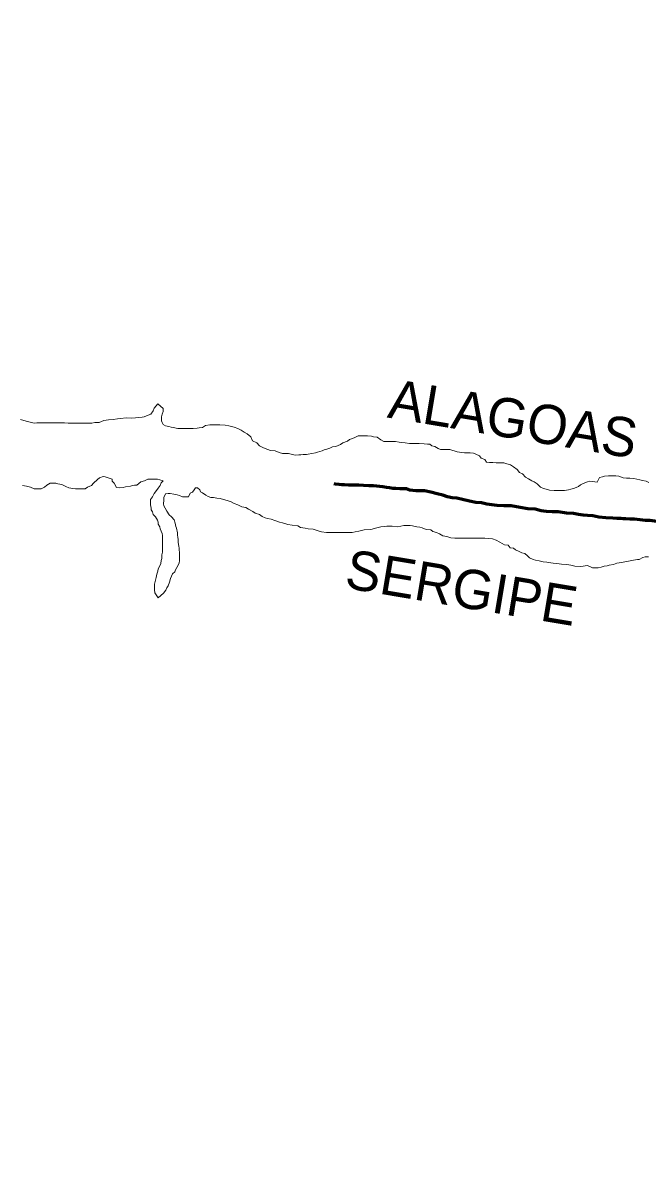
# Model space of a CAD drawing. Extents: x -1643653 to 4543381, y 1624270 to 13878484.
# Drawn here: x 657461 to 663836, y 8915829 to 8927410 of the extents above; entities that cross this region are included whole.
import ezdxf
from ezdxf.enums import TextEntityAlignment as Align

# ---------------------------------------------------------------- set-up
doc = ezdxf.new("R2010")
doc.units = 0
doc.header["$LTSCALE"] = 200
doc.linetypes.add('LONG_DASH_SHORT_DASH', pattern=[9.9, 6, -1.2, 1.5, -1.2])
for name, color, linetype, lineweight in [('23', 7, 'Continuous', 13), ('25', 7, 'Continuous', 13), ('60', 7, 'Continuous', 13), ('7', 7, 'LONG_DASH_SHORT_DASH', 60)]:
    doc.layers.add(name, color=color, linetype=linetype, lineweight=lineweight)
doc.layers.add('42', color=7, linetype='Continuous')

msp = doc.modelspace()

# ---------------------------------------------------------------- linework, layer by layer
at = {"layer": '23'}
for points in [[(660111.1, 8923015.3), (660078.7, 8923025.6), (660038.8, 8923043.3), (659988.8, 8923048.7), (659963.8, 8923056.4), (659919, 8923074.2), (659876.6, 8923094.5), (659849.3, 8923124.7), (659807, 8923147.5), (659789.7, 8923185.2), (659752.5, 8923218), (659720.1, 8923235.7), (659690.2, 8923256), (659655.3, 8923271.2), (659617.9, 8923284), (659565.5, 8923299.3), (659528.1, 8923307.1), (659473.1, 8923310), (659425.5, 8923310.3), (659370.5, 8923308.1), (659327.9, 8923300.9), (659295.3, 8923283.6), (659262.7, 8923278.8), (659240.2, 8923273.9), (659200.1, 8923271.7), (659177.6, 8923271.9), (659142.6, 8923272.1), (659120.1, 8923272.2), (659075.1, 8923272.5), (659045.1, 8923272.7), (658997.6, 8923280.6), (658975.1, 8923285.7), (658952.7, 8923290.9), (658917.7, 8923298.6), (658895.3, 8923311.3), (658883, 8923331.4), (658878.1, 8923351.4), (658878.2, 8923371.5), (658878.4, 8923391.5), (658886.1, 8923419), (658893.8, 8923444), (658894.1, 8923476.5), (658839.4, 8923524.4), (658801.5, 8923479.6), (658791.3, 8923452.2), (658768.6, 8923417.3), (658741, 8923407.4), (658700.8, 8923390.2), (658680.8, 8923387.8), (658645.7, 8923383), (658610.7, 8923380.8), (658568.2, 8923378.5), (658518.2, 8923378.9), (658460.6, 8923374.2), (658428, 8923369.5), (658383, 8923364.7), (658337.9, 8923360), (658290.3, 8923352.8), (658242.7, 8923333.1), (658197.7, 8923333.4), (658167.6, 8923326.1), (658110.1, 8923326.5), (658082.6, 8923326.7), (658027.5, 8923327), (657992.5, 8923327.3), (657945, 8923327.6), (657925, 8923327.7), (657887.5, 8923328), (657862.5, 8923328.1), (657805, 8923328.5), (657732.4, 8923329), (657664.9, 8923329.4), (657624.9, 8923329.7), (657604.9, 8923329.8), (657577.3, 8923327.5), (657495, 8923348.1), (657437.6, 8923363.5)], [(660111.1, 8923015.3), (660078.7, 8923025.6), (660038.8, 8923043.3), (659988.8, 8923048.7), (659963.8, 8923056.4), (659919, 8923074.2), (659876.6, 8923094.5), (659849.3, 8923124.7), (659807, 8923147.5), (659789.7, 8923185.2), (659752.5, 8923218), (659720.1, 8923235.7), (659690.2, 8923256), (659655.3, 8923271.2), (659617.9, 8923284), (659565.5, 8923299.3), (659528.1, 8923307.1), (659473.1, 8923310), (659425.5, 8923310.3), (659370.5, 8923308.1), (659327.9, 8923300.9), (659295.3, 8923283.6), (659262.7, 8923278.8), (659240.2, 8923273.9), (659200.1, 8923271.7), (659177.6, 8923271.9), (659142.6, 8923272.1), (659120.1, 8923272.2), (659075.1, 8923272.5), (659045.1, 8923272.7), (658997.6, 8923280.6), (658975.1, 8923285.7), (658952.7, 8923290.9), (658917.7, 8923298.6), (658895.3, 8923311.3), (658883, 8923331.4), (658878.1, 8923351.4), (658878.2, 8923371.5), (658878.4, 8923391.5), (658886.1, 8923419), (658893.8, 8923444), (658894.1, 8923476.5), (658839.4, 8923524.4), (658801.5, 8923479.6), (658791.3, 8923452.2), (658768.6, 8923417.3), (658741, 8923407.4), (658700.8, 8923390.2), (658680.8, 8923387.8), (658645.7, 8923383), (658610.7, 8923380.8), (658568.2, 8923378.5), (658518.2, 8923378.9), (658460.6, 8923374.2), (658428, 8923369.5), (658383, 8923364.7), (658337.9, 8923360), (658290.3, 8923352.8), (658242.7, 8923333.1), (658197.7, 8923333.4), (658167.6, 8923326.1), (658110.1, 8923326.5), (658082.6, 8923326.7), (658027.5, 8923327), (657992.5, 8923327.3), (657945, 8923327.6), (657925, 8923327.7), (657887.5, 8923328), (657862.5, 8923328.1), (657805, 8923328.5), (657732.4, 8923329), (657664.9, 8923329.4), (657624.9, 8923329.7), (657604.9, 8923329.8), (657577.3, 8923327.5), (657495, 8923348.1), (657437.6, 8923363.5)], [(663378.2, 8922778.4), (663348.2, 8922771.1), (663325.3, 8922723.7), (663250.3, 8922734.2), (663225.3, 8922729.4), (663182.6, 8922712.1), (663155, 8922697.3), (663134.9, 8922679.9), (663094.7, 8922662.6), (663054.6, 8922652.9), (663032.1, 8922645.5), (662992, 8922640.8), (662969.5, 8922638.4), (662937, 8922638.6), (662917, 8922638.8), (662884.5, 8922639), (662839.5, 8922644.3), (662804.5, 8922652), (662777.1, 8922659.7), (662747.2, 8922674.9), (662712.4, 8922707.7), (662680, 8922728), (662657.6, 8922738.1), (662625.2, 8922758.4), (662592.9, 8922776.1), (662563.1, 8922808.8), (662530.7, 8922824.1), (662508.4, 8922854.3), (662471.1, 8922879.6), (662438.7, 8922899.8), (662401.3, 8922912.6), (662371.4, 8922922.8), (662333.9, 8922923), (662313.9, 8922923.2), (662293.8, 8922923.3), (662258.8, 8922923.5), (662226.3, 8922923.7), (662193.8, 8922928.9), (662176.5, 8922954.1), (662141.6, 8922969.4), (662121.8, 8922992), (662086.9, 8923009.8), (662062, 8923019.9), (662029.5, 8923022.7), (662009.5, 8923022.8), (661972, 8923023.1), (661942, 8923025.8), (661919.5, 8923030.9), (661897, 8923033.6), (661819.7, 8923056.6), (661754.6, 8923057), (661724.6, 8923057.2), (661702.2, 8923067.4), (661667.3, 8923087.7), (661637.4, 8923095.4), (661615, 8923110.5), (661592.5, 8923113.2), (661557.5, 8923115.9), (661507.5, 8923118.8), (661472.5, 8923119), (661447.5, 8923119.2), (661407.5, 8923119.4), (661365, 8923127.2), (661327.5, 8923130), (661305, 8923132.6), (661265, 8923137.9), (661245, 8923138), (661207.5, 8923138.3), (661187.5, 8923138.4), (661147.5, 8923138.7), (661115.1, 8923156.4), (661077.8, 8923181.7), (661042.8, 8923186.9), (661020.4, 8923194.6), (660980.4, 8923197.3), (660940.3, 8923197.6), (660915.3, 8923197.8), (660885.3, 8923198), (660842.6, 8923175.7), (660797.5, 8923161), (660774.9, 8923143.6), (660729.7, 8923126.4), (660704.6, 8923109.1), (660656.9, 8923089.3), (660624.3, 8923084.5), (660596.7, 8923069.7), (660564.1, 8923059.9), (660536.6, 8923052.6), (660516.5, 8923042.7), (660493.9, 8923037.8), (660471.4, 8923030.5), (660448.8, 8923023.1), (660411.2, 8923018.4), (660376.2, 8923008.6), (660356.1, 8923006.2), (660323.6, 8923006.4), (660301.1, 8923004.1), (660281.1, 8923004.2), (660243.5, 8922999.4), (660173.6, 8923017.4), (660111.1, 8923015.3)], [(663378.2, 8922778.4), (663348.2, 8922771.1), (663325.3, 8922723.7), (663250.3, 8922734.2), (663225.3, 8922729.4), (663182.6, 8922712.1), (663155, 8922697.3), (663134.9, 8922679.9), (663094.7, 8922662.6), (663054.6, 8922652.9), (663032.1, 8922645.5), (662992, 8922640.8), (662969.5, 8922638.4), (662937, 8922638.6), (662917, 8922638.8), (662884.5, 8922639), (662839.5, 8922644.3), (662804.5, 8922652), (662777.1, 8922659.7), (662747.2, 8922674.9), (662712.4, 8922707.7), (662680, 8922728), (662657.6, 8922738.1), (662625.2, 8922758.4), (662592.9, 8922776.1), (662563.1, 8922808.8), (662530.7, 8922824.1), (662508.4, 8922854.3), (662471.1, 8922879.6), (662438.7, 8922899.8), (662401.3, 8922912.6), (662371.4, 8922922.8), (662333.9, 8922923), (662313.9, 8922923.2), (662293.8, 8922923.3), (662258.8, 8922923.5), (662226.3, 8922923.7), (662193.8, 8922928.9), (662176.5, 8922954.1), (662141.6, 8922969.4), (662121.8, 8922992), (662086.9, 8923009.8), (662062, 8923019.9), (662029.5, 8923022.7), (662009.5, 8923022.8), (661972, 8923023.1), (661942, 8923025.8), (661919.5, 8923030.9), (661897, 8923033.6), (661819.7, 8923056.6), (661754.6, 8923057), (661724.6, 8923057.2), (661702.2, 8923067.4), (661667.3, 8923087.7), (661637.4, 8923095.4), (661615, 8923110.5), (661592.5, 8923113.2), (661557.5, 8923115.9), (661507.5, 8923118.8), (661472.5, 8923119), (661447.5, 8923119.2), (661407.5, 8923119.4), (661365, 8923127.2), (661327.5, 8923130), (661305, 8923132.6), (661265, 8923137.9), (661245, 8923138), (661207.5, 8923138.3), (661187.5, 8923138.4), (661147.5, 8923138.7), (661115.1, 8923156.4), (661077.8, 8923181.7), (661042.8, 8923186.9), (661020.4, 8923194.6), (660980.4, 8923197.3), (660940.3, 8923197.6), (660915.3, 8923197.8), (660885.3, 8923198), (660842.6, 8923175.7), (660797.5, 8923161), (660774.9, 8923143.6), (660729.7, 8923126.4), (660704.6, 8923109.1), (660656.9, 8923089.3), (660624.3, 8923084.5), (660596.7, 8923069.7), (660564.1, 8923059.9), (660536.6, 8923052.6), (660516.5, 8923042.7), (660493.9, 8923037.8), (660471.4, 8923030.5), (660448.8, 8923023.1), (660411.2, 8923018.4), (660376.2, 8923008.6), (660356.1, 8923006.2), (660323.6, 8923006.4), (660301.1, 8923004.1), (660281.1, 8923004.2), (660243.5, 8922999.4), (660173.6, 8923017.4), (660111.1, 8923015.3)], [(663850.5, 8922720.2), (663825.6, 8922735.4), (663785.6, 8922740.7), (663760.7, 8922748.3), (663730.7, 8922753.6), (663698.2, 8922761.3), (663658.2, 8922764.1), (663623.2, 8922764.3), (663588.2, 8922767), (663545.9, 8922787.3), (663513.3, 8922787.5), (663478.4, 8922790.3), (663440.8, 8922790.5), (663398.3, 8922785.8), (663378.2, 8922778.4)], [(663850.5, 8922720.2), (663825.6, 8922735.4), (663785.6, 8922740.7), (663760.7, 8922748.3), (663730.7, 8922753.6), (663698.2, 8922761.3), (663658.2, 8922764.1), (663623.2, 8922764.3), (663588.2, 8922767), (663545.9, 8922787.3), (663513.3, 8922787.5), (663478.4, 8922790.3), (663440.8, 8922790.5), (663398.3, 8922785.8), (663378.2, 8922778.4)]]:
    msp.add_lwpolyline(points, dxfattribs=at)
at = {"layer": '25'}
for points in [[(657437.6, 8923363.5), (657495, 8923348.1), (657577.3, 8923327.5), (657604.9, 8923329.8), (657624.9, 8923329.7), (657664.9, 8923329.4), (657732.4, 8923329), (657805, 8923328.5), (657862.5, 8923328.1), (657887.5, 8923328), (657925, 8923327.7), (657945, 8923327.6), (657992.5, 8923327.3), (658027.5, 8923327), (658082.6, 8923326.7), (658110.1, 8923326.5), (658167.6, 8923326.1), (658197.7, 8923333.4), (658242.7, 8923333.1), (658290.3, 8923352.8), (658337.9, 8923360), (658383, 8923364.7), (658428, 8923369.5), (658460.6, 8923374.2), (658518.2, 8923378.9), (658568.2, 8923378.5), (658610.7, 8923380.8), (658645.7, 8923383), (658680.8, 8923387.8), (658700.8, 8923390.2), (658741, 8923407.4), (658768.6, 8923417.3), (658791.3, 8923452.2), (658801.5, 8923479.6), (658839.4, 8923524.4), (658894.1, 8923476.5), (658893.8, 8923444), (658886.1, 8923419), (658878.4, 8923391.5), (658878.2, 8923371.5), (658878.1, 8923351.4), (658883, 8923331.4), (658895.3, 8923311.3), (658917.7, 8923298.6), (658952.7, 8923290.9), (658975.1, 8923285.7), (658997.6, 8923280.6), (659045.1, 8923272.7), (659075.1, 8923272.5), (659120.1, 8923272.2), (659142.6, 8923272.1), (659177.6, 8923271.9), (659200.1, 8923271.7), (659240.2, 8923273.9), (659262.7, 8923278.8), (659295.3, 8923283.6), (659327.9, 8923300.9), (659370.5, 8923308.1), (659425.5, 8923310.3), (659473.1, 8923310), (659528.1, 8923307.1), (659565.5, 8923299.3), (659617.9, 8923284), (659655.3, 8923271.2), (659690.2, 8923256), (659720.1, 8923235.7), (659752.5, 8923218), (659789.7, 8923185.2), (659807, 8923147.5), (659849.3, 8923124.7), (659876.6, 8923094.5), (659919, 8923074.2), (659963.8, 8923056.4), (659988.8, 8923048.7), (660038.8, 8923043.3), (660078.7, 8923025.6), (660111.1, 8923015.3)], [(660111.1, 8923015.3), (660173.6, 8923017.4), (660243.5, 8922999.4), (660281.1, 8923004.2), (660301.1, 8923004.1), (660323.6, 8923006.4), (660356.1, 8923006.2), (660376.2, 8923008.6), (660411.2, 8923018.4), (660448.8, 8923023.1), (660471.4, 8923030.5), (660493.9, 8923037.8), (660516.5, 8923042.7), (660536.6, 8923052.6), (660564.1, 8923059.9), (660596.7, 8923069.7), (660624.3, 8923084.5), (660656.9, 8923089.3), (660704.6, 8923109.1), (660729.7, 8923126.4), (660774.9, 8923143.6), (660797.5, 8923161), (660842.6, 8923175.7), (660885.3, 8923198), (660915.3, 8923197.8), (660940.3, 8923197.6), (660980.4, 8923197.3), (661020.4, 8923194.6), (661042.8, 8923186.9), (661077.8, 8923181.7), (661115.1, 8923156.4), (661147.5, 8923138.7), (661187.5, 8923138.4), (661207.5, 8923138.3), (661245, 8923138), (661265, 8923137.9), (661305, 8923132.6), (661327.5, 8923130), (661365, 8923127.2), (661407.5, 8923119.4), (661447.5, 8923119.2), (661472.5, 8923119), (661507.5, 8923118.8), (661557.5, 8923115.9), (661592.5, 8923113.2), (661615, 8923110.5), (661637.4, 8923095.4), (661667.3, 8923087.7), (661702.2, 8923067.4), (661724.6, 8923057.2), (661754.6, 8923057), (661819.7, 8923056.6), (661897, 8923033.6), (661919.5, 8923030.9), (661942, 8923025.8), (661972, 8923023.1), (662009.5, 8923022.8), (662029.5, 8923022.7), (662062, 8923019.9), (662086.9, 8923009.8), (662121.8, 8922992), (662141.6, 8922969.4), (662176.5, 8922954.1), (662193.8, 8922928.9), (662226.3, 8922923.7), (662258.8, 8922923.5), (662293.8, 8922923.3), (662313.9, 8922923.2), (662333.9, 8922923), (662371.4, 8922922.8), (662401.3, 8922912.6), (662438.7, 8922899.8), (662471.1, 8922879.6), (662508.4, 8922854.3), (662530.7, 8922824.1), (662563.1, 8922808.8), (662592.9, 8922776.1), (662625.2, 8922758.4), (662657.6, 8922738.1), (662680, 8922728), (662712.4, 8922707.7), (662747.2, 8922674.9), (662777.1, 8922659.7), (662804.5, 8922652), (662839.5, 8922644.3), (662884.5, 8922639), (662917, 8922638.8), (662937, 8922638.6), (662969.5, 8922638.4), (662992, 8922640.8), (663032.1, 8922645.5), (663054.6, 8922652.9), (663094.7, 8922662.6), (663134.9, 8922679.9), (663155, 8922697.3), (663182.6, 8922712.1), (663225.3, 8922729.4), (663250.3, 8922734.2), (663325.3, 8922723.7), (663348.2, 8922771.1), (663378.2, 8922778.4)], [(658100, 8922655.6), (658065, 8922655.8), (658042.5, 8922656), (657999.9, 8922656.3), (657972.4, 8922659), (657932.5, 8922666.7), (657900.1, 8922679.5), (657860.2, 8922702.3), (657820.2, 8922707.5), (657797.8, 8922715.2), (657762.8, 8922715.4), (657742.8, 8922715.6), (657707.6, 8922693.3), (657684.9, 8922673.4), (657649.8, 8922656.1), (657629.8, 8922656.2), (657609.8, 8922656.3), (657577.2, 8922656.6), (657542.3, 8922671.8), (657499.9, 8922682.1), (657460, 8922689.9)], [(658980.7, 8922371.9), (659008, 8922339.2), (659017.7, 8922306.6), (659025, 8922274), (659032.3, 8922253.9), (659039.5, 8922208.8), (659041.8, 8922183.7), (659044.1, 8922163.7), (659046.5, 8922141.1), (659048.7, 8922108.6), (659055.9, 8922071), (659058.3, 8922050.9), (659058.1, 8922030.9), (659060.5, 8922010.9), (659060.3, 8921988.3), (659060.1, 8921955.8), (659059.8, 8921920.7), (659057.2, 8921900.7), (659047, 8921878.3), (659034.3, 8921853.3), (659021.6, 8921830.9), (659013.9, 8921808.4), (658991.3, 8921791), (658981.1, 8921766), (658970.9, 8921743.6), (658960.6, 8921703.6), (658945.3, 8921668.6), (658932.7, 8921646.2), (658922.5, 8921623.7), (658899.7, 8921591.3), (658844.4, 8921546.6), (658809.7, 8921594.4), (658807.5, 8921627), (658807.6, 8921649.5), (658807.9, 8921684.6), (658815.7, 8921724.6), (658823.4, 8921752.1), (658828.7, 8921787.1), (658838.9, 8921817.1), (658844.1, 8921842.1), (658856.8, 8921864.5), (658869.5, 8921894.5), (658874.8, 8921924.5), (658879.9, 8921947), (658882.7, 8921982), (658887.9, 8922012), (658888.2, 8922042), (658888.3, 8922064.6), (658888.6, 8922097.1), (658888.8, 8922132.2), (658889, 8922152.2), (658889.2, 8922182.2), (658884.4, 8922202.3), (658864.7, 8922247.5), (658859.9, 8922270.1), (658845.1, 8922297.7), (658842.7, 8922317.7), (658835.4, 8922337.8), (658818.1, 8922370.5), (658793.3, 8922393.2), (658786, 8922420.8), (658773.6, 8922440.9), (658771.3, 8922460.9), (658766.5, 8922493.5), (658766.8, 8922523.5), (658767, 8922548.6), (658784.7, 8922576), (658802.4, 8922608.4), (658827.7, 8922640.8), (658845.4, 8922663.2), (658863.1, 8922690.6), (658875.8, 8922718.1), (658896, 8922738), (658861, 8922748.2), (658836, 8922753.4), (658803.5, 8922753.6), (658778.5, 8922753.8), (658738.5, 8922754), (658705.8, 8922736.7), (658665.8, 8922729.5), (658645.6, 8922712.1), (658625.5, 8922694.7), (658603, 8922694.8), (658580.4, 8922690), (658560.4, 8922682.6), (658510.3, 8922675.4), (658485.2, 8922670.6), (658452.7, 8922668.3), (658417.7, 8922671), (658395.5, 8922713.7), (658375.7, 8922733.9), (658373.3, 8922753.9), (658343.4, 8922764.2), (658303.5, 8922779.4), (658281, 8922782.1), (658243.4, 8922767.3), (658223.2, 8922752.4), (658182.9, 8922712.7), (658162.8, 8922690.2), (658122.6, 8922673), (658100, 8922655.6)], [(663378.2, 8922778.4), (663398.3, 8922785.8), (663440.8, 8922790.5), (663478.4, 8922790.3), (663513.3, 8922787.5), (663545.9, 8922787.3), (663588.2, 8922767), (663623.2, 8922764.3), (663658.2, 8922764.1), (663698.2, 8922761.3), (663730.7, 8922753.6), (663760.7, 8922748.3), (663785.6, 8922740.7), (663825.6, 8922735.4), (663850.5, 8922720.2)], [(662255.4, 8922147.4), (662220.4, 8922150.2), (662177.9, 8922153), (662152.9, 8922153.1), (662112.9, 8922153.4), (662087.9, 8922153.6), (662027.9, 8922154), (661975.4, 8922154.3), (661940.3, 8922154.5), (661900.3, 8922154.8), (661872.8, 8922155), (661830.3, 8922155.3), (661790.4, 8922170.6), (661750.4, 8922175.8), (661715.6, 8922196.1), (661683.2, 8922211.3), (661648.2, 8922221.6), (661625.8, 8922236.7), (661578.3, 8922242.1), (661538.5, 8922257.3), (661516, 8922265), (661483.5, 8922270.2), (661441.1, 8922278), (661416.1, 8922283.2), (661373.6, 8922283.5), (661351.1, 8922283.6), (661290.9, 8922269), (661233.5, 8922274.4), (661178.4, 8922274.7), (661150.9, 8922272.4), (661115.8, 8922267.6), (661075.8, 8922260.4), (661015.6, 8922243.3), (660945.6, 8922238.7), (660892.9, 8922224.1), (660852.8, 8922216.8), (660825.3, 8922212), (660772.8, 8922209.8), (660732.7, 8922210.1), (660682.7, 8922210.4), (660637.7, 8922210.7), (660610.2, 8922210.9), (660560.2, 8922211.2), (660510.2, 8922219.1), (660475.2, 8922226.8), (660425.4, 8922244.7), (660375.4, 8922247.5), (660342.9, 8922255.2), (660295.5, 8922263.1), (660268.1, 8922280.8), (660213.1, 8922286.1), (660165.6, 8922294), (660113.2, 8922309.3), (660080.8, 8922317.1), (660035.9, 8922332.4), (659996, 8922347.7), (659958.5, 8922352.9), (659936, 8922360.6), (659903.6, 8922375.8), (659878.8, 8922393.5), (659833.8, 8922408.8), (659809, 8922424), (659766.6, 8922449.3), (659739.3, 8922467), (659699.3, 8922472.3), (659656.9, 8922492.6), (659619.5, 8922505.4), (659587.1, 8922525.6), (659547.2, 8922538.4), (659509.8, 8922546.2), (659477.3, 8922556.4), (659442.3, 8922561.6), (659407.4, 8922566.8), (659382.4, 8922569.5), (659354.9, 8922577.2), (659330, 8922592.4), (659297.7, 8922615.2), (659275.2, 8922625.3), (659267.9, 8922645.4), (659245.6, 8922665.6), (659223.1, 8922668.2), (659210.4, 8922645.8), (659195.2, 8922623.3), (659170.1, 8922611), (659152.3, 8922576.1), (659117.3, 8922576.3), (659092.3, 8922573.9), (659059.9, 8922589.2), (659037.4, 8922594.3), (659002.5, 8922602.1), (658967.5, 8922607.3), (658945, 8922610), (658920, 8922605.1), (658902.2, 8922567.7), (658902, 8922540.2), (658899.2, 8922502.6), (658901.5, 8922482.6), (658913.8, 8922460), (658933.6, 8922427.3), (658955.8, 8922392.1), (658980.7, 8922371.9)], [(663096.2, 8921869), (663056.2, 8921876.8), (663013.8, 8921884.6), (662958.8, 8921889.9), (662913.8, 8921895.2), (662873.8, 8921898), (662851.3, 8921903.2), (662811.4, 8921908.4), (662773.9, 8921913.7), (662733.9, 8921921.5), (662696.5, 8921929.2), (662671.5, 8921936.9), (662634.1, 8921952.2), (662611.8, 8921972.3), (662586.9, 8921997.5), (662557, 8922002.8), (662529.6, 8922017.9), (662492.2, 8922033.2), (662469.8, 8922050.9), (662434.8, 8922056.1), (662415, 8922081.3), (662380, 8922084), (662332.7, 8922111.9), (662292.8, 8922132.2), (662255.4, 8922147.4)], [(663849.7, 8921964.2), (663814.7, 8921964.4), (663792.2, 8921957), (663754.5, 8921937.2), (663734.5, 8921937.4), (663696.9, 8921930.1), (663661.8, 8921922.8), (663626.8, 8921915.6), (663606.7, 8921910.7), (663571.7, 8921905.9), (663524.1, 8921898.7), (663491.5, 8921883.9), (663446.4, 8921879.2), (663426.3, 8921871.8), (663396.3, 8921867), (663366.2, 8921857.2), (663333.7, 8921852.4), (663311.1, 8921850.1), (663276.1, 8921850.3), (663226.3, 8921875.7), (663156.2, 8921863.6), (663096.2, 8921869)]]:
    msp.add_lwpolyline(points, dxfattribs=at)
at = {"layer": '60', "lineweight": 25}
msp.add_spline([(814781, 9009175.5), (814787.2, 9009173.4), (814796.9, 9009173.4), (814799.4, 9009172.4), (814805.1, 9009174.5), (814805.6, 9009176.5), (814811.7, 9009179.5), (814811.7, 9009179.5), (814801.5, 9009181), (814790.7, 9009181.5), (814784.1, 9009183.1), (814777.4, 9009185.1), (814778.4, 9009175.5)], degree=3, dxfattribs=at)
at = {"layer": '7'}
for points in [[(663706.2, 8922345.6), (663656.3, 8922348.3), (663616.3, 8922351.1), (663591.3, 8922351.2), (663566.3, 8922353.8), (663526.3, 8922354), (663483.8, 8922356.8), (663411.3, 8922362.1), (663341.4, 8922367.5), (663281.5, 8922380.3), (663226.5, 8922383.1), (663181.5, 8922388.4), (663134.1, 8922393.7), (663081.6, 8922406.4), (663011.7, 8922409.3), (662926.8, 8922422.3), (662864.2, 8922422.6), (662806.8, 8922425.4), (662751.8, 8922430.7), (662691.9, 8922448.5), (662617, 8922453.9), (662539.5, 8922466.8), (662447.1, 8922482.4), (662372.1, 8922482.8), (662304.7, 8922488.1), (662249.7, 8922493.4), (662197.2, 8922498.7), (662142.3, 8922514), (662087.4, 8922516.8), (662020, 8922529.7), (661950.1, 8922547.6), (661892.6, 8922560.4), (661845.2, 8922563.1), (661797.8, 8922575.9), (661750.3, 8922591.1), (661690.5, 8922606.5), (661625.6, 8922621.8), (661563.1, 8922634.7), (661478.2, 8922637.6), (661413.2, 8922643), (661378.3, 8922655.7), (661338.3, 8922655.9), (661310.8, 8922656), (661268.3, 8922658.8), (661238.3, 8922661.4), (661205.8, 8922666.6), (661175.9, 8922669.3), (661135.9, 8922677), (661105.9, 8922679.6), (661076, 8922682.3), (661041, 8922687.5), (660993.5, 8922687.7), (660941, 8922690.5), (660893.5, 8922693.3), (660841, 8922693.6), (660786, 8922693.8), (660746, 8922696.6), (660718.5, 8922696.7), (660691.1, 8922701.8), (660648.6, 8922704.6), (660641.7, 8922706.3)], [(664555.3, 8922251.1), (664510.5, 8922233.7), (664455.6, 8922249), (664420.6, 8922251.7), (664375.7, 8922254.4), (664325.7, 8922267.2), (664288.3, 8922282.4), (664250.9, 8922287.6), (664213.5, 8922300.3), (664176, 8922305.6), (664128.6, 8922318.3), (664086.1, 8922318.5), (664048.6, 8922321.2), (663973.6, 8922324.1), (663908.6, 8922327), (663861.2, 8922332.2), (663816.2, 8922335), (663763.7, 8922340.3), (663706.2, 8922345.6)]]:
    msp.add_lwpolyline(points, dxfattribs=at)

# ---------------------------------------------------------------- texts
at = {"layer": '42'}
for s, p in [('ALAGOAS', (662435, 8923174.8)), ('SERGIPE', (661908.6, 8921452.5))]:
    msp.add_text(s, height=400, rotation=350.533, dxfattribs=at).set_placement(p, align=Align.CENTER)

doc.saveas('drawing.dxf')
